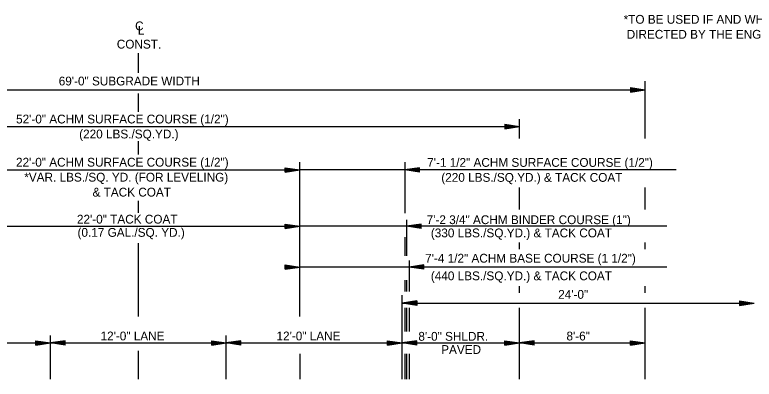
# Model space of a CAD drawing. Extents: x 1371763 to 1372860, y 385599 to 385872.
# Drawn here: x 1372352.1 to 1372402.6, y 385624.1 to 385648.9 of the extents above; entities that cross this region are included whole.
import ezdxf

# ---------------------------------------------------------------- set-up
doc = ezdxf.new("R2010")
doc.units = 0
doc.layers.add('R_Draft', color=7, linetype='Continuous')

msp = doc.modelspace()

# ---------------------------------------------------------------- linework, layer by layer
at = {"layer": 'R_Draft'}
for p, q in [((1372360.579, 385644.935), (1372360.579, 385646.285)), ((1372394.148, 385643.935), (1372395.148, 385643.785)), ((1372394.148, 385643.935), (1372394.148, 385643.635)), ((1372395.148, 385640.475), (1372395.148, 385644.385)), ((1372326.012, 385643.785), (1372395.148, 385643.785)), ((1372360.579, 385642.285), (1372360.579, 385643.535)), ((1372394.148, 385643.91), (1372394.981, 385643.785)), ((1372394.148, 385643.884), (1372394.809, 385643.785)), ((1372394.148, 385643.859), (1372394.643, 385643.785)), ((1372394.148, 385643.833), (1372394.473, 385643.785)), ((1372394.148, 385643.808), (1372394.306, 385643.785)), ((1372394.148, 385643.635), (1372395.148, 385643.785)), ((1372394.148, 385643.736), (1372394.473, 385643.785)), ((1372394.148, 385643.685), (1372394.809, 385643.785)), ((1372394.148, 385643.66), (1372394.981, 385643.785)), ((1372394.148, 385643.71), (1372394.643, 385643.785)), ((1372394.148, 385643.761), (1372394.306, 385643.785)), ((1372385.577, 385641.435), (1372386.577, 385641.285)), ((1372385.577, 385641.435), (1372385.577, 385641.135)), ((1372385.577, 385641.41), (1372386.41, 385641.285)), ((1372386.577, 385640.475), (1372386.577, 385641.795)), ((1372334.576, 385641.285), (1372386.577, 385641.285)), ((1372385.577, 385641.384), (1372386.238, 385641.285)), ((1372385.577, 385641.359), (1372386.071, 385641.285)), ((1372385.577, 385641.333), (1372385.902, 385641.285)), ((1372385.577, 385641.308), (1372385.735, 385641.285)), ((1372385.577, 385641.135), (1372386.577, 385641.285)), ((1372385.577, 385641.236), (1372385.902, 385641.285)), ((1372385.577, 385641.185), (1372386.238, 385641.285)), ((1372385.577, 385641.16), (1372386.41, 385641.285)), ((1372385.577, 385641.21), (1372386.071, 385641.285)), ((1372385.577, 385641.261), (1372385.735, 385641.285)), ((1372360.579, 385639.376), (1372360.579, 385640.285)), ((1372370.579, 385638.479), (1372371.579, 385638.329)), ((1372370.579, 385638.179), (1372370.579, 385638.479)), ((1372370.579, 385638.454), (1372371.412, 385638.329)), ((1372370.579, 385638.429), (1372371.24, 385638.329)), ((1372370.579, 385638.404), (1372371.074, 385638.329)), ((1372370.579, 385638.378), (1372370.904, 385638.329)), ((1372371.578, 385628.342), (1372371.579, 385638.851)), ((1372378.748, 385638.851), (1372378.748, 385635.372)), ((1372379.748, 385638.479), (1372378.748, 385638.329)), ((1372379.748, 385638.454), (1372378.915, 385638.329)), ((1372379.748, 385638.429), (1372379.087, 385638.329)), ((1372379.748, 385638.404), (1372379.253, 385638.329)), ((1372379.748, 385638.378), (1372379.423, 385638.329)), ((1372379.748, 385638.179), (1372379.748, 385638.479)), ((1372349.579, 385638.329), (1372371.579, 385638.329)), ((1372370.579, 385638.353), (1372370.737, 385638.329)), ((1372370.579, 385638.179), (1372371.579, 385638.329)), ((1372370.579, 385638.281), (1372370.904, 385638.329)), ((1372370.579, 385638.23), (1372371.24, 385638.329)), ((1372370.579, 385638.204), (1372371.412, 385638.329)), ((1372370.579, 385638.255), (1372371.074, 385638.329)), ((1372370.579, 385638.306), (1372370.737, 385638.329)), ((1372397.255, 385638.329), (1372371.579, 385638.329)), ((1372379.748, 385638.179), (1372378.748, 385638.329)), ((1372379.748, 385638.204), (1372378.915, 385638.329)), ((1372379.748, 385638.23), (1372379.087, 385638.329)), ((1372379.748, 385638.255), (1372379.253, 385638.329)), ((1372379.748, 385638.281), (1372379.423, 385638.329)), ((1372379.748, 385638.353), (1372379.59, 385638.329)), ((1372379.748, 385638.306), (1372379.59, 385638.329)), ((1372386.577, 385635.621), (1372386.577, 385637.121)), ((1372395.148, 385635.621), (1372395.148, 385637.121)), ((1372360.576, 385635.404), (1372360.576, 385636.215)), ((1372378.874, 385634.935), (1372378.874, 385632.483)), ((1372349.579, 385634.485), (1372371.579, 385634.485)), ((1372370.579, 385634.635), (1372371.579, 385634.485)), ((1372370.579, 385634.335), (1372370.579, 385634.635)), ((1372370.579, 385634.61), (1372371.412, 385634.485)), ((1372370.579, 385634.584), (1372371.24, 385634.485)), ((1372370.579, 385634.559), (1372371.074, 385634.485)), ((1372370.579, 385634.534), (1372370.904, 385634.485)), ((1372370.579, 385634.508), (1372370.737, 385634.485)), ((1372370.579, 385634.335), (1372371.579, 385634.485)), ((1372370.579, 385634.436), (1372370.904, 385634.485)), ((1372370.579, 385634.385), (1372371.24, 385634.485)), ((1372370.579, 385634.36), (1372371.412, 385634.485)), ((1372370.579, 385634.41), (1372371.074, 385634.485)), ((1372370.579, 385634.461), (1372370.737, 385634.485)), ((1372396.621, 385634.485), (1372371.579, 385634.485)), ((1372379.874, 385634.635), (1372378.874, 385634.485)), ((1372379.874, 385634.335), (1372378.874, 385634.485)), ((1372379.874, 385634.61), (1372379.041, 385634.485)), ((1372379.874, 385634.36), (1372379.041, 385634.485)), ((1372379.874, 385634.585), (1372379.213, 385634.485)), ((1372379.874, 385634.386), (1372379.213, 385634.485)), ((1372379.874, 385634.56), (1372379.379, 385634.485)), ((1372379.874, 385634.411), (1372379.379, 385634.485)), ((1372379.874, 385634.534), (1372379.549, 385634.485)), ((1372379.874, 385634.437), (1372379.549, 385634.485)), ((1372379.874, 385634.509), (1372379.716, 385634.485)), ((1372379.874, 385634.462), (1372379.716, 385634.485)), ((1372379.874, 385634.335), (1372379.874, 385634.635)), ((1372360.577, 385628.344), (1372360.576, 385633.34)), ((1372378.748, 385633.735), (1372378.748, 385632.483)), ((1372386.577, 385632.924), (1372386.577, 385633.389)), ((1372395.148, 385632.924), (1372395.148, 385633.389)), ((1372370.578, 385631.86), (1372371.578, 385631.71)), ((1372370.578, 385631.56), (1372370.578, 385631.86)), ((1372370.578, 385631.835), (1372371.411, 385631.71)), ((1372379.042, 385632.16), (1372379.042, 385630.044)), ((1372380.042, 385631.86), (1372379.042, 385631.71)), ((1372380.042, 385631.835), (1372379.209, 385631.71)), ((1372380.042, 385631.56), (1372380.042, 385631.86)), ((1372370.578, 385631.809), (1372371.239, 385631.71)), ((1372370.578, 385631.784), (1372371.073, 385631.71)), ((1372370.578, 385631.759), (1372370.903, 385631.71)), ((1372370.578, 385631.733), (1372370.736, 385631.71)), ((1372370.578, 385631.56), (1372371.578, 385631.71)), ((1372370.578, 385631.661), (1372370.903, 385631.71)), ((1372370.578, 385631.61), (1372371.239, 385631.71)), ((1372370.578, 385631.585), (1372371.411, 385631.71)), ((1372370.578, 385631.635), (1372371.073, 385631.71)), ((1372370.578, 385631.686), (1372370.736, 385631.71)), ((1372396.621, 385631.71), (1372371.579, 385631.71)), ((1372380.042, 385631.56), (1372379.042, 385631.71)), ((1372380.042, 385631.585), (1372379.209, 385631.71)), ((1372380.042, 385631.809), (1372379.381, 385631.71)), ((1372380.042, 385631.61), (1372379.381, 385631.71)), ((1372380.042, 385631.784), (1372379.548, 385631.71)), ((1372380.042, 385631.635), (1372379.548, 385631.71)), ((1372380.042, 385631.759), (1372379.717, 385631.71)), ((1372380.042, 385631.661), (1372379.717, 385631.71)), ((1372380.042, 385631.733), (1372379.884, 385631.71)), ((1372380.042, 385631.686), (1372379.884, 385631.71)), ((1372378.748, 385630.809), (1372378.748, 385630.044)), ((1372378.874, 385630.809), (1372378.874, 385630.044)), ((1372386.577, 385629.95), (1372386.577, 385630.416)), ((1372395.148, 385629.95), (1372395.148, 385630.416)), ((1372378.576, 385624.074), (1372378.577, 385629.787)), ((1372379.577, 385629.397), (1372378.577, 385629.247)), ((1372379.577, 385629.372), (1372378.744, 385629.247)), ((1372379.577, 385629.346), (1372378.916, 385629.247)), ((1372379.577, 385629.321), (1372379.082, 385629.247)), ((1372379.577, 385629.295), (1372379.252, 385629.247)), ((1372379.577, 385629.397), (1372379.577, 385629.097)), ((1372401.577, 385629.397), (1372402.577, 385629.247)), ((1372401.577, 385629.397), (1372401.577, 385629.097)), ((1372401.577, 385629.372), (1372402.41, 385629.247)), ((1372401.577, 385629.346), (1372402.238, 385629.247)), ((1372401.577, 385629.321), (1372402.071, 385629.247)), ((1372401.577, 385629.295), (1372401.902, 385629.247)), ((1372378.577, 385629.247), (1372402.577, 385629.247)), ((1372379.577, 385629.097), (1372378.577, 385629.247)), ((1372379.577, 385629.122), (1372378.744, 385629.247)), ((1372378.748, 385628.936), (1372378.748, 385627.327)), ((1372378.874, 385628.936), (1372378.874, 385627.327)), ((1372379.577, 385629.147), (1372378.916, 385629.247)), ((1372379.042, 385628.936), (1372379.042, 385627.327)), ((1372379.577, 385629.172), (1372379.082, 385629.247)), ((1372379.577, 385629.198), (1372379.252, 385629.247)), ((1372379.577, 385629.27), (1372379.419, 385629.247)), ((1372379.577, 385629.223), (1372379.419, 385629.247)), ((1372386.576, 385624.068), (1372386.577, 385628.935)), ((1372395.148, 385624.068), (1372395.148, 385628.933)), ((1372401.577, 385629.27), (1372401.735, 385629.247)), ((1372401.577, 385629.097), (1372402.577, 385629.247)), ((1372401.577, 385629.198), (1372401.902, 385629.247)), ((1372401.577, 385629.147), (1372402.238, 385629.247)), ((1372401.577, 385629.122), (1372402.41, 385629.247)), ((1372401.577, 385629.172), (1372402.071, 385629.247)), ((1372401.577, 385629.223), (1372401.735, 385629.247)), ((1372354.576, 385624.074), (1372354.576, 385627.047)), ((1372366.576, 385624.074), (1372366.576, 385627.047)), ((1372342.576, 385626.54), (1372354.576, 385626.54)), ((1372353.576, 385626.69), (1372354.576, 385626.54)), ((1372353.576, 385626.39), (1372353.576, 385626.69)), ((1372353.576, 385626.665), (1372354.409, 385626.54)), ((1372353.576, 385626.64), (1372354.237, 385626.54)), ((1372353.576, 385626.615), (1372354.071, 385626.54)), ((1372353.576, 385626.589), (1372353.901, 385626.54)), ((1372353.576, 385626.564), (1372353.734, 385626.54)), ((1372353.576, 385626.39), (1372354.576, 385626.54)), ((1372353.576, 385626.492), (1372353.901, 385626.54)), ((1372353.576, 385626.441), (1372354.237, 385626.54)), ((1372353.576, 385626.415), (1372354.409, 385626.54)), ((1372353.576, 385626.466), (1372354.071, 385626.54)), ((1372353.576, 385626.517), (1372353.734, 385626.54)), ((1372355.576, 385626.69), (1372354.576, 385626.54)), ((1372355.576, 385626.39), (1372354.576, 385626.54)), ((1372354.576, 385626.54), (1372366.576, 385626.54)), ((1372355.576, 385626.665), (1372354.743, 385626.54)), ((1372355.576, 385626.415), (1372354.743, 385626.54)), ((1372355.576, 385626.64), (1372354.915, 385626.54)), ((1372355.576, 385626.441), (1372354.915, 385626.54)), ((1372355.576, 385626.615), (1372355.082, 385626.54)), ((1372355.576, 385626.466), (1372355.082, 385626.54)), ((1372355.576, 385626.589), (1372355.251, 385626.54)), ((1372355.576, 385626.492), (1372355.251, 385626.54)), ((1372355.576, 385626.564), (1372355.418, 385626.54)), ((1372355.576, 385626.517), (1372355.418, 385626.54)), ((1372355.576, 385626.39), (1372355.576, 385626.69)), ((1372365.576, 385626.69), (1372366.576, 385626.54)), ((1372365.576, 385626.39), (1372365.576, 385626.69)), ((1372365.576, 385626.665), (1372366.409, 385626.54)), ((1372365.576, 385626.64), (1372366.237, 385626.54)), ((1372365.576, 385626.615), (1372366.071, 385626.54)), ((1372365.576, 385626.589), (1372365.901, 385626.54)), ((1372365.576, 385626.564), (1372365.734, 385626.54)), ((1372365.576, 385626.39), (1372366.576, 385626.54)), ((1372365.576, 385626.492), (1372365.901, 385626.54)), ((1372365.576, 385626.441), (1372366.237, 385626.54)), ((1372365.576, 385626.415), (1372366.409, 385626.54)), ((1372365.576, 385626.466), (1372366.071, 385626.54)), ((1372365.576, 385626.517), (1372365.734, 385626.54)), ((1372367.576, 385626.69), (1372366.576, 385626.54)), ((1372366.576, 385626.54), (1372378.576, 385626.54)), ((1372367.576, 385626.39), (1372366.576, 385626.54)), ((1372367.576, 385626.665), (1372366.743, 385626.54)), ((1372367.576, 385626.415), (1372366.743, 385626.54)), ((1372367.576, 385626.64), (1372366.915, 385626.54)), ((1372367.576, 385626.441), (1372366.915, 385626.54)), ((1372367.576, 385626.615), (1372367.082, 385626.54)), ((1372367.576, 385626.466), (1372367.082, 385626.54)), ((1372367.576, 385626.589), (1372367.251, 385626.54)), ((1372367.576, 385626.492), (1372367.251, 385626.54)), ((1372367.576, 385626.564), (1372367.418, 385626.54)), ((1372367.576, 385626.517), (1372367.418, 385626.54)), ((1372367.576, 385626.39), (1372367.576, 385626.69)), ((1372377.576, 385626.69), (1372378.576, 385626.54)), ((1372377.576, 385626.39), (1372377.576, 385626.69)), ((1372377.576, 385626.665), (1372378.409, 385626.54)), ((1372377.576, 385626.64), (1372378.237, 385626.54)), ((1372377.576, 385626.615), (1372378.071, 385626.54)), ((1372377.576, 385626.589), (1372377.901, 385626.54)), ((1372377.576, 385626.564), (1372377.734, 385626.54)), ((1372377.576, 385626.39), (1372378.576, 385626.54)), ((1372377.576, 385626.492), (1372377.901, 385626.54)), ((1372377.576, 385626.441), (1372378.237, 385626.54)), ((1372377.576, 385626.415), (1372378.409, 385626.54)), ((1372377.576, 385626.466), (1372378.071, 385626.54)), ((1372377.576, 385626.517), (1372377.734, 385626.54)), ((1372379.576, 385626.69), (1372378.576, 385626.54)), ((1372379.576, 385626.39), (1372378.576, 385626.54)), ((1372378.576, 385626.54), (1372386.576, 385626.54)), ((1372379.576, 385626.665), (1372378.743, 385626.54)), ((1372379.576, 385626.415), (1372378.743, 385626.54)), ((1372379.576, 385626.64), (1372378.915, 385626.54)), ((1372379.576, 385626.441), (1372378.915, 385626.54)), ((1372379.576, 385626.615), (1372379.082, 385626.54)), ((1372379.576, 385626.466), (1372379.082, 385626.54)), ((1372379.576, 385626.589), (1372379.251, 385626.54)), ((1372379.576, 385626.492), (1372379.251, 385626.54)), ((1372379.576, 385626.564), (1372379.418, 385626.54)), ((1372379.576, 385626.517), (1372379.418, 385626.54)), ((1372379.576, 385626.39), (1372379.576, 385626.69)), ((1372385.576, 385626.69), (1372386.576, 385626.54)), ((1372385.576, 385626.39), (1372385.576, 385626.69)), ((1372385.576, 385626.665), (1372386.409, 385626.54)), ((1372385.576, 385626.64), (1372386.237, 385626.54)), ((1372385.576, 385626.615), (1372386.071, 385626.54)), ((1372385.576, 385626.589), (1372385.901, 385626.54)), ((1372385.576, 385626.564), (1372385.734, 385626.54)), ((1372385.576, 385626.39), (1372386.576, 385626.54)), ((1372385.576, 385626.492), (1372385.901, 385626.54)), ((1372385.576, 385626.441), (1372386.237, 385626.54)), ((1372385.576, 385626.415), (1372386.409, 385626.54)), ((1372385.576, 385626.466), (1372386.071, 385626.54)), ((1372385.576, 385626.517), (1372385.734, 385626.54)), ((1372387.576, 385626.69), (1372386.576, 385626.54)), ((1372387.576, 385626.39), (1372386.576, 385626.54)), ((1372386.576, 385626.54), (1372395.148, 385626.539)), ((1372387.576, 385626.665), (1372386.743, 385626.54)), ((1372387.576, 385626.415), (1372386.743, 385626.54)), ((1372387.576, 385626.64), (1372386.915, 385626.54)), ((1372387.576, 385626.441), (1372386.915, 385626.54)), ((1372387.576, 385626.615), (1372387.082, 385626.54)), ((1372387.576, 385626.466), (1372387.082, 385626.54)), ((1372387.576, 385626.589), (1372387.251, 385626.54)), ((1372387.576, 385626.492), (1372387.251, 385626.54)), ((1372387.576, 385626.564), (1372387.418, 385626.54)), ((1372387.576, 385626.517), (1372387.418, 385626.54)), ((1372387.576, 385626.39), (1372387.576, 385626.69)), ((1372394.148, 385626.689), (1372395.148, 385626.539)), ((1372394.148, 385626.389), (1372394.148, 385626.689)), ((1372394.148, 385626.664), (1372394.981, 385626.539)), ((1372394.148, 385626.639), (1372394.809, 385626.539)), ((1372394.148, 385626.614), (1372394.642, 385626.539)), ((1372394.148, 385626.588), (1372394.473, 385626.539)), ((1372394.148, 385626.563), (1372394.306, 385626.539)), ((1372394.148, 385626.389), (1372395.148, 385626.539)), ((1372394.148, 385626.491), (1372394.473, 385626.539)), ((1372394.148, 385626.44), (1372394.809, 385626.539)), ((1372394.148, 385626.414), (1372394.981, 385626.539)), ((1372394.148, 385626.465), (1372394.642, 385626.539)), ((1372394.148, 385626.516), (1372394.306, 385626.539)), ((1372360.577, 385624.069), (1372360.577, 385626.01)), ((1372371.578, 385625.79), (1372371.578, 385624.074)), ((1372378.748, 385625.79), (1372378.748, 385624.074)), ((1372378.874, 385625.79), (1372378.874, 385624.074)), ((1372379.042, 385625.79), (1372379.042, 385624.074))]:
    msp.add_line(p, q, dxfattribs=at)

# ---------------------------------------------------------------- texts
for s, rotation, p in [('*TO BE USED IF AND WHERE ', 360, (1372393.671, 385648.289)), ('C', 360, (1372360.354, 385647.841)), ('L', 360, (1372360.541, 385647.541)), ('DIRECTED BY THE ENGINEER', 360, (1372393.881, 385647.269)), ('CONST.', 360, (1372359.106, 385646.597)), ('69\'-0" SUBGRADE WIDTH', 360, (1372355.146, 385644.085)), ('52\'-0" ACHM SURFACE COURSE (1/2")', 360, (1372352.236, 385641.495)), ('(220 LBS./SQ.YD.)', 360, (1372356.54, 385640.475)), ('22\'-0" ACHM SURFACE COURSE (1/2")', 360, (1372352.233, 385638.553)), ('7\'-1 1/2" ACHM SURFACE COURSE (1/2")', 0, (1372380.275, 385638.539)), ('*VAR. LBS./SQ. YD. (FOR LEVELING)', 360, (1372352.795, 385637.533)), ('(220 LBS./SQ.YD.) & TACK COAT', 0, (1372381.237, 385637.519)), ('& TACK COAT', 360, (1372357.451, 385636.513)), ('22\'-0" TACK COAT', 360, (1372356.388, 385634.671)), ('7\'-2 3/4" ACHM BINDER COURSE (1")', 0, (1372380.239, 385634.635)), ('(0.17 GAL./SQ. YD.)', 360, (1372356.428, 385633.771)), ('(330 LBS./SQ.YD.) & TACK COAT', 0, (1372380.524, 385633.735)), ('7\'-4 1/2" ACHM BASE COURSE (1 1/2")', 360, (1372380.135, 385632.01)), ('(440 LBS./SQ.YD.) & TACK COAT', 360, (1372380.524, 385630.81)), ('12\'-0" LANE', 360, (1372357.998, 385626.712)), ('12\'-0" LANE', 360, (1372369.998, 385626.712)), ('8\'-0" SHLDR.', 360, (1372379.673, 385626.689)), ('8\'-6"', 360, (1372389.773, 385626.71)), ('PAVED', 360, (1372381.23, 385625.789))]:
    msp.add_text(s, height=0.6, rotation=rotation, dxfattribs=at).set_placement(p)
msp.add_text('24\'-0"', height=0.6, dxfattribs=at).set_placement((1372389.209, 385629.547))

doc.saveas('drawing.dxf')
